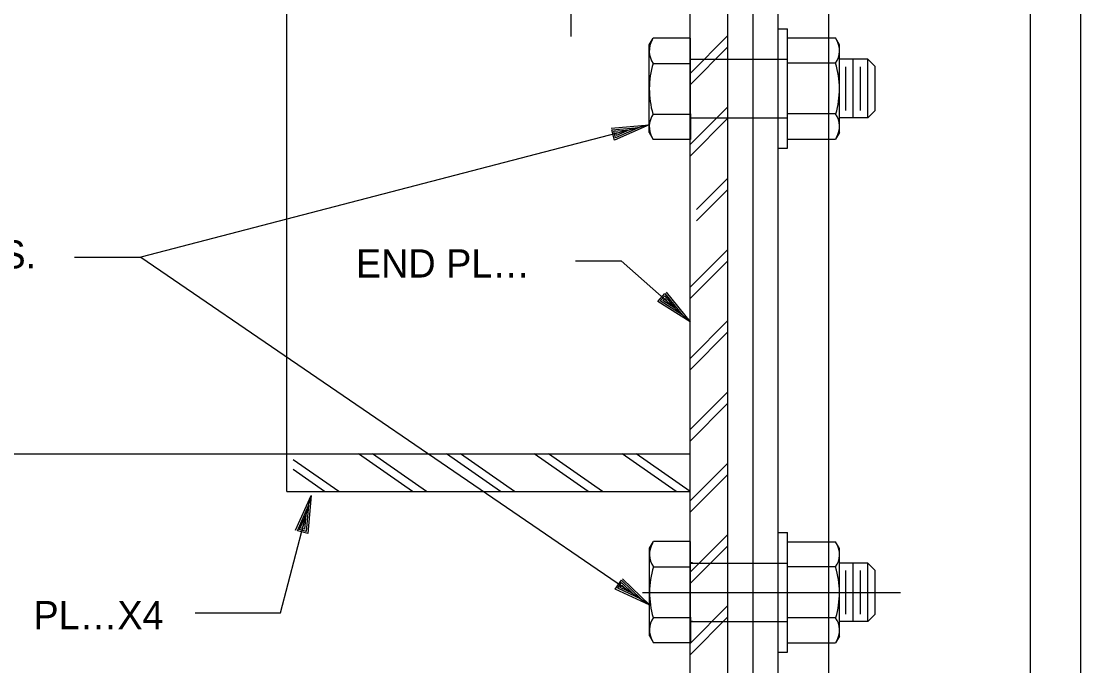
# Model space of a CAD drawing. Extents: x 18232 to 22378, y 12454 to 22381.
# Drawn here: x 22374.829 to 22375.705, y 22372.06 to 22372.593 of the extents above; entities that cross this region are included whole.
import ezdxf

# ---------------------------------------------------------------- set-up
doc = ezdxf.new("R2010")
doc.units = 0
for name, color, linetype in [('Level 2', 7, 'Continuous'), ('Level 3', 7, 'Continuous'), ('Level 50', 7, 'Continuous')]:
    doc.layers.add(name, color=color, linetype=linetype)

msp = doc.modelspace()

# ---------------------------------------------------------------- linework, layer by layer
at = {"layer": 'Level 2'}
for p, q in [((22375.04854, 22372.20408), (22375.04854, 22372.99575)), ((22375.38188, 22371.86033), (22375.38188, 22372.99575)), ((22375.41313, 22371.82908), (22375.41313, 22372.99575)), ((22375.43396, 22371.80825), (22375.43396, 22372.99575)), ((22375.66313, 22371.66242), (22375.66313, 22372.92283)), ((22375.70479, 22371.53742), (22375.70479, 22372.92283)), ((22375.49646, 22371.78742), (22375.49646, 22372.74923)), ((22375.45479, 22371.78742), (22375.45479, 22372.63117)), ((22375.45479, 22372.58678), (22375.46229, 22372.58678)), ((22375.46229, 22372.48805), (22375.46229, 22372.58678)), ((22375.34814, 22372.57348), (22375.35139, 22372.5791)), ((22375.34814, 22372.50098), (22375.34814, 22372.57348)), ((22375.38207, 22372.5791), (22375.35139, 22372.5791)), ((22375.38207, 22372.49535), (22375.38207, 22372.5791)), ((22375.46229, 22372.57928), (22375.50204, 22372.57928)), ((22375.50529, 22372.57368), (22375.50204, 22372.57928)), ((22375.50529, 22372.50116), (22375.50529, 22372.57368)), ((22375.3513, 22372.55821), (22375.38207, 22372.55821)), ((22375.38207, 22372.56168), (22375.46229, 22372.56168)), ((22375.38359, 22372.56148), (22375.38207, 22372.56148)), ((22375.50213, 22372.55839), (22375.46229, 22372.55839)), ((22375.52873, 22372.56168), (22375.50529, 22372.56168)), ((22375.51056, 22372.5193), (22375.51056, 22372.55536)), ((22375.5166, 22372.51318), (22375.5166, 22372.56168)), ((22375.52267, 22372.5193), (22375.52267, 22372.55536)), ((22375.52873, 22372.51318), (22375.52873, 22372.56168)), ((22375.52873, 22372.56168), (22375.53479, 22372.55561)), ((22375.53479, 22372.51924), (22375.53479, 22372.55561)), ((22375.52873, 22372.51318), (22375.53479, 22372.51924)), ((22375.3513, 22372.51625), (22375.38207, 22372.51625)), ((22375.38207, 22372.51654), (22375.38207, 22372.49535)), ((22375.38207, 22372.51318), (22375.46229, 22372.51318)), ((22375.38359, 22372.51298), (22375.38207, 22372.51298)), ((22375.50213, 22372.51645), (22375.46229, 22372.51645)), ((22375.52873, 22372.51318), (22375.50529, 22372.51318)), ((22375.50529, 22372.50116), (22375.50204, 22372.49555)), ((22375.34814, 22372.50098), (22375.35139, 22372.49535)), ((22375.38207, 22372.49535), (22375.35139, 22372.49535)), ((22375.46229, 22372.49555), (22375.50204, 22372.49555)), ((22375.45479, 22372.48805), (22375.46229, 22372.48805)), ((22374.10219, 22372.23533), (22375.05375, 22372.23533)), ((22375.05375, 22372.23533), (22375.38188, 22372.23533)), ((22375.04854, 22372.20408), (22375.38188, 22372.20408)), ((22375.45479, 22372.17011), (22375.46229, 22372.17011)), ((22375.46229, 22372.07139), (22375.46229, 22372.17011)), ((22375.34835, 22372.15715), (22375.3516, 22372.16277)), ((22375.38229, 22372.16277), (22375.3516, 22372.16277)), ((22375.38229, 22372.07902), (22375.38229, 22372.16277)), ((22375.46229, 22372.16261), (22375.50204, 22372.16261)), ((22375.50529, 22372.15701), (22375.50204, 22372.16261)), ((22375.34835, 22372.08465), (22375.34835, 22372.15715)), ((22375.50529, 22372.08449), (22375.50529, 22372.15701)), ((22375.38381, 22372.14515), (22375.38229, 22372.14515)), ((22375.38229, 22372.14501), (22375.46229, 22372.14501)), ((22375.52873, 22372.14501), (22375.50529, 22372.14501)), ((22375.5166, 22372.09651), (22375.5166, 22372.14501)), ((22375.52873, 22372.09651), (22375.52873, 22372.14501)), ((22375.52873, 22372.14501), (22375.53479, 22372.13895)), ((22375.35152, 22372.14188), (22375.38229, 22372.14188)), ((22375.50213, 22372.14172), (22375.46229, 22372.14172)), ((22375.51056, 22372.10264), (22375.51056, 22372.1387)), ((22375.52267, 22372.10264), (22375.52267, 22372.1387)), ((22375.53479, 22372.10257), (22375.53479, 22372.13895)), ((22375.34251, 22372.12075), (22375.55568, 22372.12075)), ((22375.35152, 22372.09992), (22375.38229, 22372.09992)), ((22375.38229, 22372.10021), (22375.38229, 22372.07902)), ((22375.50213, 22372.09978), (22375.46229, 22372.09978)), ((22375.52873, 22372.09651), (22375.53479, 22372.10257)), ((22375.38381, 22372.09665), (22375.38229, 22372.09665)), ((22375.38229, 22372.09651), (22375.46229, 22372.09651)), ((22375.52873, 22372.09651), (22375.50529, 22372.09651)), ((22375.34835, 22372.08465), (22375.3516, 22372.07902)), ((22375.50529, 22372.08449), (22375.50204, 22372.07889)), ((22375.38229, 22372.07902), (22375.3516, 22372.07902)), ((22375.46229, 22372.07889), (22375.50204, 22372.07889)), ((22375.45479, 22372.07139), (22375.46229, 22372.07139))]:
    msp.add_line(p, q, dxfattribs=at)
for centre, radius, start, end in [((22375.36629, 22372.5685), 0.01818, 149.71241, 214.51098), ((22375.48714, 22372.5687), 0.01818, 325.48902, 30.28759), ((22375.42087, 22372.53696), 0.07273, 163.01837, 196.49659), ((22375.43257, 22372.53715), 0.07273, 343.50341, 16.98163), ((22375.36629, 22372.50596), 0.01818, 145.48902, 210.28759), ((22375.48714, 22372.50615), 0.01818, 329.71241, 34.51098), ((22375.36651, 22372.15217), 0.01818, 149.71241, 214.51098), ((22375.48714, 22372.15203), 0.01818, 325.48902, 30.28759), ((22375.42108, 22372.12062), 0.07273, 163.01837, 196.49659), ((22375.43257, 22372.12048), 0.07273, 343.50341, 16.98163), ((22375.36651, 22372.08962), 0.01818, 145.48902, 210.28759), ((22375.48714, 22372.08948), 0.01818, 329.71241, 34.51098)]:
    msp.add_arc(centre, radius, start, end, dxfattribs=at)
at = {"layer": 'Level 3'}
for p, q in [((22375.28359, 22372.58048), (22375.28359, 22372.63117)), ((22375.34814, 22372.50746), (22374.92791, 22372.39806)), ((22374.8732, 22372.39806), (22374.92791, 22372.39806)), ((22374.92791, 22372.39806), (22375.3487, 22372.11017)), ((22375.2871, 22372.39491), (22375.325, 22372.39491)), ((22375.38188, 22372.34455), (22375.325, 22372.39491)), ((22375.04342, 22372.10371), (22375.06866, 22372.20094)), ((22375.06866, 22372.20094), (22375.06866, 22372.20094)), ((22375.06648, 22372.19255), (22375.06648, 22372.19255)), ((22375.34154, 22372.11506), (22375.34154, 22372.11506)), ((22375.3487, 22372.11017), (22375.3487, 22372.11017)), ((22374.97283, 22372.10371), (22375.04342, 22372.10371))]:
    msp.add_line(p, q, dxfattribs=at)
for points in [[(22375.38188, 22372.54994), (22375.41313, 22372.58119)], [(22375.38188, 22372.54051), (22375.41313, 22372.57176)], [(22375.38188, 22372.49101), (22375.41313, 22372.52227)], [(22375.38188, 22372.48158), (22375.41313, 22372.51284)], [(22375.38708, 22372.43729), (22375.41313, 22372.46334)], [(22375.38708, 22372.42786), (22375.41313, 22372.45392)], [(22375.38188, 22372.37317), (22375.41313, 22372.40442)], [(22375.38188, 22372.36373), (22375.41313, 22372.39499)], [(22375.38188, 22372.31424), (22375.41313, 22372.34549)], [(22375.38188, 22372.30481), (22375.41314, 22372.33607)], [(22375.38188, 22372.25531), (22375.41314, 22372.28657)], [(22375.38188, 22372.24589), (22375.41313, 22372.27714)], [(22375.09144, 22372.20408), (22375.05376, 22372.23046)], [(22375.15246, 22372.20407), (22375.10782, 22372.23533)], [(22375.16408, 22372.20407), (22375.11944, 22372.23533)], [(22375.22509, 22372.20408), (22375.18047, 22372.23533)], [(22375.23673, 22372.20408), (22375.19209, 22372.23533)], [(22375.29774, 22372.20408), (22375.2531, 22372.23533)], [(22375.30936, 22372.20408), (22375.26473, 22372.23533)], [(22375.37039, 22372.20408), (22375.32575, 22372.23533)], [(22375.38201, 22372.20408), (22375.33738, 22372.23533)], [(22375.07981, 22372.20408), (22375.05376, 22372.22232)], [(22375.38188, 22372.19639), (22375.41313, 22372.22764)], [(22375.38188, 22372.18696), (22375.41314, 22372.21822)], [(22375.05582, 22372.17207), (22375.06866, 22372.20094), (22375.06582, 22372.16947), (22375.05728, 22372.17169), (22375.06648, 22372.19255), (22375.06455, 22372.17118), (22375.05906, 22372.1726), (22375.06439, 22372.18448), (22375.06327, 22372.1729), (22375.06101, 22372.17348), (22375.06221, 22372.17609)], [(22375.38188, 22372.13746), (22375.41313, 22372.16871)], [(22375.38188, 22372.12803), (22375.41313, 22372.15928)], [(22375.3259, 22372.13203), (22375.3487, 22372.11017), (22375.32006, 22372.1235), (22375.32504, 22372.13079), (22375.34154, 22372.11506), (22375.3221, 22372.12413), (22375.3253, 22372.1288), (22375.33467, 22372.11977), (22375.32415, 22372.12475), (22375.32546, 22372.12668), (22375.32751, 22372.12466)], [(22375.38188, 22372.07853), (22375.41313, 22372.10979)], [(22375.38188, 22372.0691), (22375.41313, 22372.10036)]]:
    msp.add_lwpolyline(points, dxfattribs=at)
at = {"layer": 'Level 50'}
for p, q in [((22375.33975, 22372.50527), (22375.33975, 22372.50527)), ((22375.34814, 22372.50746), (22375.34814, 22372.50746)), ((22375.37539, 22372.3503), (22375.37539, 22372.3503)), ((22375.38188, 22372.34455), (22375.38188, 22372.34455))]:
    msp.add_line(p, q, dxfattribs=at)
for points in [[(22375.31668, 22372.5046), (22375.34814, 22372.50746), (22375.31927, 22372.4946), (22375.31705, 22372.50316), (22375.33975, 22372.50527), (22375.32015, 22372.49655), (22375.31872, 22372.50204), (22375.33169, 22372.50318), (22375.32102, 22372.4985), (22375.32043, 22372.50076), (22375.32329, 22372.50099)], [(22375.36197, 22372.36908), (22375.38188, 22372.34455), (22375.35511, 22372.36134), (22375.36097, 22372.36796), (22375.37539, 22372.3503), (22375.35722, 22372.36171), (22375.36098, 22372.36595), (22375.36915, 22372.35582), (22375.35932, 22372.36207), (22375.36086, 22372.36382), (22375.36266, 22372.36156)]]:
    msp.add_lwpolyline(points, dxfattribs=at)

# ---------------------------------------------------------------- texts
at = {"layer": 'Level 3'}
for s, height, p in [('W/WASHERS, C.R.S.', 0.0233333, (22374.53623, 22372.38858)), ('END PL… ', 0.023333, (22375.10568, 22372.3811)), ('PL…X4', 0.023333, (22374.83916, 22372.09022))]:
    msp.add_text(s, height=height, dxfattribs=at).set_placement(p)

doc.saveas('drawing.dxf')
